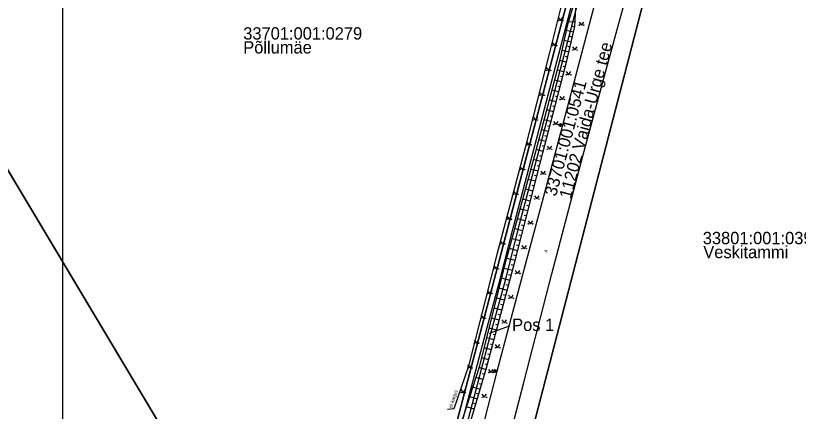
# Model space of a CAD drawing. Extents: x 554947 to 555436, y 6564938 to 6565792.
# Drawn here: x 555042.9 to 555195.6, y 6565056.2 to 6565133.3 of the extents above; entities that cross this region are included whole.
import ezdxf

# ---------------------------------------------------------------- set-up
doc = ezdxf.new("R2010")
doc.units = 0
for name, color, linetype in [('AED', 7, 'Continuous'), ('HALJASTUS', 7, 'Continuous'), ('KASUTUSALA', 7, 'Continuous'), ('PIIR', 7, 'Continuous'), ('POST', 7, 'Continuous'), ('PR_SIDE', 7, 'Continuous'), ('RELJEEF', 7, 'Continuous'), ('TEE', 7, 'Continuous'), ('VORMISTUS', 7, 'Continuous')]:
    doc.layers.add(name, color=color, linetype=linetype)

msp = doc.modelspace()

# ---------------------------------------------------------------- linework, layer by layer
at = {"layer": 'AED'}
msp.add_lwpolyline([(555179.37, 6565300.08), (555180.24, 6565299.85), (555180.75, 6565290.87), (555180.14, 6565280.62), (555178.98, 6565264.79), (555177.98, 6565255.29), (555177.31, 6565249.05), (555173.49, 6565227.42), (555169.73, 6565212.42), (555163.78, 6565189.53), (555156.09, 6565161.76), (555151.43, 6565143.9), (555146.99, 6565125.89), (555142.27, 6565107.51), (555136.77, 6565086.76), (555131.21, 6565064.98), (555128.39, 6565056.62), (555127.14, 6565056.52)], dxfattribs=at)
at = {"layer": 'HALJASTUS'}
for p, q in [((555148.74, 6565132.95), (555149.2, 6565132.34)), ((555149.2, 6565132.34), (555149.64, 6565132.95)), ((555152.81, 6565132.06), (555153.28, 6565131.45)), ((555153.28, 6565131.45), (555153.72, 6565132.06)), ((555147.54, 6565128.1), (555148, 6565127.49)), ((555148, 6565127.49), (555148.45, 6565128.1)), ((555151.52, 6565127.23), (555151.98, 6565126.62)), ((555151.98, 6565126.62), (555152.42, 6565127.23)), ((555146.34, 6565123.24), (555146.81, 6565122.63)), ((555146.81, 6565122.63), (555147.25, 6565123.24)), ((555150.28, 6565122.39), (555150.74, 6565121.78)), ((555150.74, 6565121.78), (555151.19, 6565122.39)), ((555145.11, 6565118.4), (555145.57, 6565117.79)), ((555145.57, 6565117.79), (555146.02, 6565118.4)), ((555149.04, 6565117.54), (555149.5, 6565116.94)), ((555149.5, 6565116.94), (555149.95, 6565117.54)), ((555143.83, 6565113.56), (555144.29, 6565112.96)), ((555144.29, 6565112.96), (555144.74, 6565113.56)), ((555147.8, 6565112.7), (555148.26, 6565112.09)), ((555148.26, 6565112.09), (555148.71, 6565112.7)), ((555142.55, 6565108.73), (555143.01, 6565108.12)), ((555143.01, 6565108.12), (555143.46, 6565108.73)), ((555146.56, 6565107.86), (555147.02, 6565107.25)), ((555147.02, 6565107.25), (555147.47, 6565107.86)), ((555141.27, 6565103.9), (555141.73, 6565103.29)), ((555141.73, 6565103.29), (555142.18, 6565103.9)), ((555145.32, 6565103.01), (555145.78, 6565102.41)), ((555145.78, 6565102.41), (555146.23, 6565103.01)), ((555139.99, 6565099.06), (555140.45, 6565098.46)), ((555140.45, 6565098.46), (555140.9, 6565099.06)), ((555144.08, 6565098.17), (555144.54, 6565097.56)), ((555144.54, 6565097.56), (555144.99, 6565098.17)), ((555138.71, 6565094.23), (555139.18, 6565093.62)), ((555139.18, 6565093.62), (555139.62, 6565094.23)), ((555142.84, 6565093.32), (555143.3, 6565092.72)), ((555143.3, 6565092.72), (555143.75, 6565093.32)), ((555137.43, 6565089.39), (555137.9, 6565088.79)), ((555137.9, 6565088.79), (555138.34, 6565089.39)), ((555141.6, 6565088.48), (555142.06, 6565087.87)), ((555142.06, 6565087.87), (555142.51, 6565088.48)), ((555136.15, 6565084.56), (555136.62, 6565083.95)), ((555136.62, 6565083.95), (555137.06, 6565084.56)), ((555140.36, 6565083.64), (555140.82, 6565083.03)), ((555140.82, 6565083.03), (555141.27, 6565083.64)), ((555134.88, 6565079.73), (555135.34, 6565079.12)), ((555135.34, 6565079.12), (555135.78, 6565079.73)), ((555139.06, 6565078.81), (555139.52, 6565078.2)), ((555139.52, 6565078.2), (555139.97, 6565078.81)), ((555133.6, 6565074.89), (555134.06, 6565074.29)), ((555134.06, 6565074.29), (555134.51, 6565074.89)), ((555137.75, 6565073.98), (555138.22, 6565073.38)), ((555138.22, 6565073.38), (555138.66, 6565073.98)), ((555132.32, 6565070.06), (555132.78, 6565069.45)), ((555132.78, 6565069.45), (555133.23, 6565070.06)), ((555136.45, 6565069.16), (555136.91, 6565068.55)), ((555136.91, 6565068.55), (555137.36, 6565069.16)), ((555131.04, 6565065.23), (555131.5, 6565064.62)), ((555131.5, 6565064.62), (555131.95, 6565065.23)), ((555135.14, 6565064.33), (555135.61, 6565063.72)), ((555135.61, 6565063.72), (555136.05, 6565064.33)), ((555129.73, 6565060.4), (555130.19, 6565059.79)), ((555130.19, 6565059.79), (555130.64, 6565060.4)), ((555133.84, 6565059.5), (555134.3, 6565058.89)), ((555134.3, 6565058.89), (555134.75, 6565059.5))]:
    msp.add_line(p, q, dxfattribs=at)
for centre in [(555148.8, 6565132.34), (555149.63, 6565132.34), (555152.87, 6565131.45), (555153.7, 6565131.45), (555147.6, 6565127.49), (555148.43, 6565127.49), (555151.58, 6565126.62), (555152.41, 6565126.62), (555146.41, 6565122.63), (555147.24, 6565122.63), (555150.34, 6565121.78), (555151.17, 6565121.78), (555145.17, 6565117.79), (555146, 6565117.79), (555149.1, 6565116.94), (555149.93, 6565116.94), (555143.89, 6565112.96), (555144.72, 6565112.96), (555147.86, 6565112.09), (555148.69, 6565112.09), (555142.61, 6565108.12), (555143.44, 6565108.12), (555146.62, 6565107.25), (555147.45, 6565107.25), (555141.33, 6565103.29), (555142.16, 6565103.29), (555145.38, 6565102.41), (555146.21, 6565102.41), (555140.05, 6565098.46), (555140.88, 6565098.46), (555144.14, 6565097.56), (555144.97, 6565097.56), (555138.77, 6565093.62), (555139.6, 6565093.62), (555142.9, 6565092.72), (555143.73, 6565092.72), (555137.5, 6565088.79), (555138.32, 6565088.79), (555141.66, 6565087.87), (555142.49, 6565087.87), (555136.22, 6565083.95), (555137.05, 6565083.95), (555140.42, 6565083.03), (555141.25, 6565083.03), (555134.94, 6565079.12), (555135.77, 6565079.12), (555139.12, 6565078.2), (555139.95, 6565078.2), (555133.66, 6565074.29), (555134.49, 6565074.29), (555137.82, 6565073.38), (555138.64, 6565073.38), (555132.38, 6565069.45), (555133.21, 6565069.45), (555136.51, 6565068.55), (555137.34, 6565068.55), (555131.1, 6565064.62), (555131.93, 6565064.62), (555135.21, 6565063.72), (555136.03, 6565063.72), (555129.79, 6565059.79), (555130.62, 6565059.79), (555133.9, 6565058.89), (555134.73, 6565058.89)]:
    msp.add_circle(centre, 0.055, dxfattribs=at)
at = {"layer": 'KASUTUSALA'}
for points in [[(555181.21, 6565254.62), (555178.9, 6565239.72), (555174.64, 6565220.29), (555158.17, 6565157.51), (555170.13, 6565154.48), (555169.63, 6565152.55), (555157.92, 6565155.51), (555157.61, 6565155.41), (555157.1, 6565153.34), (555146.61, 6565113.41), (555140.88, 6565091.59), (555138.36, 6565081.69), (555135.8, 6565072.23), (555119.02, 6565008.26)], [(555127.06, 6565046.78), (555141, 6565099.93), (555152.73, 6565144.63), (555155.08, 6565153.61), (555155.89, 6565156.67), (555156.91, 6565160.58), (555162.41, 6565181.55), (555172.65, 6565220.57), (555172.7, 6565220.76), (555176.93, 6565240.07), (555176.94, 6565240.14), (555179.22, 6565254.85)]]:
    msp.add_lwpolyline(points, dxfattribs=at)
at = {"layer": 'PIIR'}
msp.add_lwpolyline([(554962.55, 6565234.93), (555180.26, 6565306.43), (555180.8, 6565287.7), (555180.41, 6565269.99), (555179.22, 6565254.85), (555176.93, 6565240.09), (555172.7, 6565220.76), (555117.14, 6565008.97), (555108.27, 6564991.27)], close=True, dxfattribs=at)
for points in [[(555195.28, 6565271.63), (555191.64, 6565237.48), (555173.84, 6565168.77), (555173.21, 6565166.35), (555172.58, 6565163.93), (555140.74, 6565041.04), (555133.32, 6565012.53), (555119.68, 6564972.95), (555107.79, 6564965.53), (555093.78, 6564958.98), (555080.97, 6564954.71), (555029.59, 6564944.2)], [(555029.59, 6564962.19), (555076.32, 6564971.61), (555087.28, 6564975.26), (555098.22, 6564980.37), (555106.03, 6564987.06), (555108.27, 6564991.27), (555117.14, 6565008.97), (555172.7, 6565220.76), (555176.93, 6565240.09), (555179.22, 6565254.85)], [(555272.01, 6565013.37), (555140.74, 6565041.04), (555172.58, 6565163.93), (555173.21, 6565166.35), (555225.89, 6565157.13), (555231.12, 6565150.64), (555239.11, 6565139), (555273.15, 6565087.34), (555275.41, 6565088.83), (555288.85, 6565092.31), (555289.83, 6565088.53), (555290.17, 6565088.22)], [(555029.59, 6565122.84), (555108.27, 6564991.27), (555106.03, 6564987.06), (555098.22, 6564980.37), (555087.28, 6564975.26), (555076.32, 6564971.61), (555029.59, 6564962.19)]]:
    msp.add_lwpolyline(points, dxfattribs=at)
at = {"layer": 'POST'}
for p, q in [((555148.99, 6565111.82), (555149.35, 6565112.17)), ((555136.2, 6565063.85), (555136.55, 6565064.2))]:
    msp.add_line(p, q, dxfattribs=at)
for centre in [(555149.17, 6565112), (555136.38, 6565064.03)]:
    msp.add_circle(centre, 0.25, dxfattribs=at)
for centre, radius, start, end in [((555149.17, 6565112), 0.225, 224.8541, 45.0356), ((555149.17, 6565112), 0.2, 224.8427, 45.047), ((555149.17, 6565112), 0.175, 224.8281, 45.0616), ((555149.17, 6565112), 0.15, 224.8087, 45.081), ((555149.17, 6565112), 0.125, 224.7814, 45.1083), ((555149.17, 6565112), 0.1, 224.7406, 45.1491), ((555149.17, 6565112), 0.075, 224.6725, 45.2172), ((555149.17, 6565112), 0.05, 224.5363, 45.3534), ((555149.17, 6565112), 0.025, 224.1278, 45.7619), ((555136.38, 6565064.03), 0.225, 224.8541, 45.0356), ((555136.38, 6565064.03), 0.2, 224.8427, 45.047), ((555136.38, 6565064.03), 0.175, 224.8281, 45.0616), ((555136.38, 6565064.03), 0.15, 224.8087, 45.081), ((555136.38, 6565064.03), 0.125, 224.7814, 45.1083), ((555136.38, 6565064.03), 0.1, 224.7406, 45.1491), ((555136.38, 6565064.03), 0.075, 224.6725, 45.2172), ((555136.38, 6565064.03), 0.05, 224.5363, 45.3534), ((555136.38, 6565064.03), 0.025, 224.1278, 45.7619)]:
    msp.add_arc(centre, radius, start, end, dxfattribs=at)
at = {"layer": 'PR_SIDE'}
msp.add_lwpolyline([(555210.99, 6564988.67), (555132.01, 6564980.72), (555127.54, 6564982.26), (555122.65, 6564985.01), (555110.84, 6564991.67), (555110.25, 6564992.99), (555118.08, 6565008.62), (555124.87, 6565034.5), (555128.06, 6565046.66), (555134.84, 6565072.49), (555137.4, 6565081.94), (555139.91, 6565091.84), (555145.64, 6565113.67), (555156.08, 6565153.41), (555155.86, 6565155.17), (555156.45, 6565155.52), (555156.83, 6565156.34), (555160.76, 6565171.32), (555163.71, 6565182.54), (555165.38, 6565188.9), (555173.67, 6565220.53), (555176.86, 6565235.1), (555177.91, 6565239.91), (555180.21, 6565254.73)], dxfattribs=at)
at = {"layer": 'RELJEEF'}
for p, q in [((555152.04, 6565132.06), (555150.74, 6565132.13)), ((555152.09, 6565133.06), (555151.78, 6565133.08)), ((555151.97, 6565131.07), (555151.54, 6565131.17)), ((555151.73, 6565130.09), (555150.32, 6565130.44)), ((555151.5, 6565129.12), (555151.08, 6565129.22)), ((555151.26, 6565128.15), (555149.9, 6565128.48)), ((555150.79, 6565126.21), (555149.47, 6565126.53)), ((555151.02, 6565127.18), (555150.62, 6565127.28)), ((555150.31, 6565124.26), (555149.04, 6565124.59)), ((555150.55, 6565125.24), (555150.16, 6565125.33)), ((555150.06, 6565123.3), (555149.68, 6565123.4)), ((555149.81, 6565122.33), (555148.53, 6565122.66)), ((555149.56, 6565121.36), (555149.17, 6565121.46)), ((555149.31, 6565120.39), (555148.02, 6565120.73)), ((555148.81, 6565118.46), (555147.51, 6565118.79)), ((555149.06, 6565119.42), (555148.67, 6565119.52)), ((555148.3, 6565116.52), (555147, 6565116.86)), ((555148.55, 6565117.49), (555148.17, 6565117.59)), ((555148.05, 6565115.55), (555147.66, 6565115.65)), ((555147.8, 6565114.58), (555146.49, 6565114.92)), ((555147.55, 6565113.62), (555147.16, 6565113.72)), ((555147.3, 6565112.65), (555145.98, 6565112.99)), ((555146.8, 6565110.71), (555145.48, 6565111.06)), ((555147.05, 6565111.68), (555146.65, 6565111.78)), ((555146.55, 6565109.74), (555146.15, 6565109.85)), ((555146.3, 6565108.78), (555144.97, 6565109.12)), ((555146.05, 6565107.81), (555145.65, 6565107.91)), ((555145.79, 6565106.84), (555144.46, 6565107.19)), ((555145.3, 6565104.9), (555143.93, 6565105.25)), ((555145.54, 6565105.87), (555145.14, 6565105.98)), ((555144.8, 6565102.97), (555143.41, 6565103.32)), ((555145.05, 6565103.94), (555144.63, 6565104.04)), ((555144.55, 6565102), (555144.13, 6565102.11)), ((555144.3, 6565101.03), (555142.88, 6565101.39)), ((555144.05, 6565100.06), (555143.62, 6565100.17)), ((555143.8, 6565099.09), (555142.36, 6565099.46)), ((555143.3, 6565097.16), (555141.83, 6565097.53)), ((555143.55, 6565098.12), (555143.11, 6565098.24)), ((555142.8, 6565095.22), (555141.31, 6565095.6)), ((555143.05, 6565096.19), (555142.61, 6565096.3)), ((555142.55, 6565094.25), (555142.1, 6565094.37)), ((555142.3, 6565093.28), (555140.78, 6565093.67)), ((555142.05, 6565092.31), (555141.59, 6565092.43)), ((555141.8, 6565091.35), (555140.26, 6565091.74)), ((555141.3, 6565089.41), (555139.73, 6565089.81)), ((555141.55, 6565090.38), (555141.08, 6565090.5)), ((555140.8, 6565087.47), (555139.2, 6565087.88)), ((555141.05, 6565088.44), (555140.58, 6565088.56)), ((555140.55, 6565086.5), (555140.07, 6565086.63)), ((555140.3, 6565085.54), (555138.68, 6565085.95)), ((555140.05, 6565084.57), (555139.57, 6565084.7)), ((555139.79, 6565083.6), (555138.19, 6565084.03)), ((555139.28, 6565081.67), (555137.7, 6565082.09)), ((555139.54, 6565082.64), (555139.06, 6565082.76)), ((555138.77, 6565079.74), (555137.21, 6565080.15)), ((555139.03, 6565080.7), (555138.55, 6565080.83)), ((555138.51, 6565078.77), (555138.05, 6565078.89)), ((555138.26, 6565077.8), (555136.72, 6565078.21)), ((555137.75, 6565075.87), (555136.23, 6565076.27)), ((555138, 6565076.84), (555137.54, 6565076.96)), ((555137.23, 6565073.94), (555135.73, 6565074.33)), ((555137.49, 6565074.9), (555137.04, 6565075.02)), ((555136.98, 6565072.97), (555136.53, 6565073.09)), ((555136.72, 6565072), (555135.24, 6565072.39)), ((555136.47, 6565071.04), (555136.03, 6565071.15)), ((555136.21, 6565070.07), (555134.75, 6565070.46)), ((555135.7, 6565068.14), (555134.26, 6565068.52)), ((555135.95, 6565069.1), (555135.52, 6565069.22)), ((555135.19, 6565066.2), (555133.77, 6565066.58)), ((555135.44, 6565067.17), (555135.01, 6565067.28)), ((555134.93, 6565065.24), (555134.51, 6565065.35)), ((555134.66, 6565064.27), (555133.28, 6565064.68)), ((555134.38, 6565063.31), (555133.96, 6565063.44)), ((555134.09, 6565062.36), (555132.67, 6565062.78)), ((555133.52, 6565060.44), (555132.06, 6565060.87)), ((555133.81, 6565061.4), (555133.38, 6565061.53)), ((555132.95, 6565058.52), (555131.46, 6565058.97)), ((555133.24, 6565059.48), (555132.79, 6565059.61)), ((555132.67, 6565057.56), (555132.21, 6565057.7)), ((555132.38, 6565056.6), (555130.85, 6565057.06))]:
    msp.add_line(p, q, dxfattribs=at)
for points in [[(555119.66, 6565010.32), (555123.71, 6565025.31), (555129.01, 6565045.27), (555134.76, 6565064.61), (555140.24, 6565085.3), (555145.72, 6565106.56), (555150.38, 6565124.53), (555152, 6565131.19), (555152.3, 6565137.3)], [(555119.66, 6565010.32), (555122.57, 6565025.47), (555127.46, 6565046.43), (555133.34, 6565064.86), (555138.64, 6565085.82), (555144.36, 6565106.83), (555149.09, 6565124.76), (555150.58, 6565131.59), (555152.3, 6565137.3)]]:
    msp.add_lwpolyline(points, dxfattribs=at)
at = {"layer": 'TEE'}
for points in [[(555183.59, 6565248.99), (555179.7, 6565227.86), (555175.39, 6565210.51), (555169.43, 6565187.48), (555162.32, 6565160.51), (555157.77, 6565142.96), (555152.67, 6565123.75), (555148, 6565106.07), (555142.31, 6565084.71), (555136.78, 6565063.94), (555131.82, 6565044.7), (555126.53, 6565024.44), (555123, 6565010.82), (555119.08, 6564999.09), (555116.16, 6564993.2), (555108.26, 6564982.26)], [(555115, 6564980.21), (555119.47, 6564986.79), (555121.43, 6564990.44), (555124.13, 6564996.67), (555128.45, 6565009.12), (555131.98, 6565022.77), (555137.23, 6565043.21), (555142.09, 6565062.04), (555147.46, 6565082.98), (555153.12, 6565104.46), (555157.98, 6565122.31), (555163.2, 6565141.62), (555168.3, 6565162.21), (555168.74, 6565163.56), (555174.48, 6565185.52), (555180.71, 6565208.97), (555185.09, 6565226.84), (555186.8, 6565233.51), (555187.91, 6565235.65)]]:
    msp.add_lwpolyline(points, dxfattribs=at)
at = {"layer": 'VORMISTUS'}
msp.add_line((555135.31, 6565071.41), (555139.25, 6565072.81), dxfattribs=at)
msp.add_lwpolyline([(555217.09, 6564974.91), (555052.09, 6564974.91), (555052.09, 6565184.91), (555217.09, 6565184.91)], close=True, dxfattribs=at)

# ---------------------------------------------------------------- texts
at = {"layer": 'AED'}
msp.add_text('el karjus', height=0.7, rotation=71.28, dxfattribs=at).set_placement((555127.99, 6565056.75))
at = {"layer": 'PIIR'}
for s, p in [('33701:001:0279', (555087.27, 6565128.65)), ('Põllumäe', (555087.27, 6565125.93)), ('33801:001:0392', (555176.94, 6565088.75)), ('Veskitammi', (555177.04, 6565086.02))]:
    msp.add_text(s, height=2.4, dxfattribs=at).set_placement(p)
for s, p in [('11202 Vaida-Urge tee', (555151.19, 6565097.44)), ('33701:001:0541', (555148.31, 6565097.95))]:
    msp.add_text(s, height=2.4, rotation=75.0195, dxfattribs=at).set_placement(p)
at = {"layer": 'TEE'}
msp.add_text('A', height=0.7, rotation=71.8158, dxfattribs=at).set_placement((555146.58, 6565087.03))
at = {"layer": 'VORMISTUS'}
msp.add_text('Pos 1', height=2.4, dxfattribs=at).set_placement((555139.74, 6565071.82))

doc.saveas('drawing.dxf')
